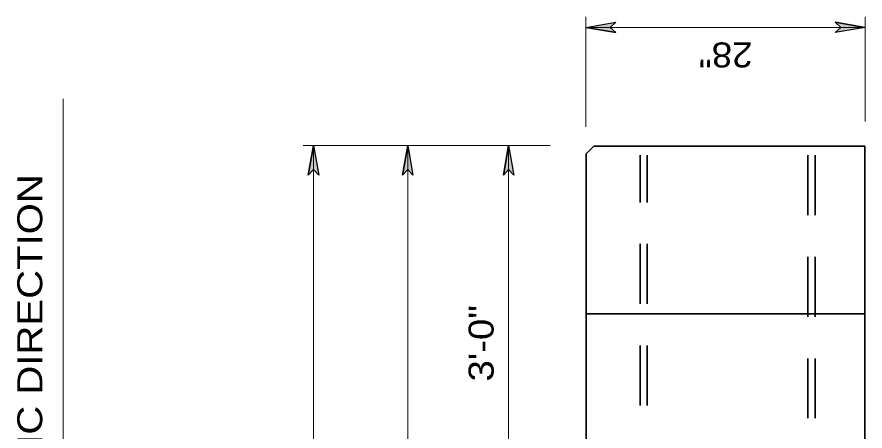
# Model space of a CAD drawing. Extents: x 12.6 to 19.5, y 6.1 to 16.3.
# Drawn here: x 14.828 to 16.866, y 12.348 to 13.343 of the extents above; entities that cross this region are included whole.
import ezdxf
from ezdxf.enums import TextEntityAlignment as Align

# ---------------------------------------------------------------- set-up
doc = ezdxf.new("R2010")
doc.units = 0
doc.header["$LTSCALE"] = 0.024
doc.linetypes.add('LONG_DASHED', pattern=[7.5, 6, -1.5])
for name, color, linetype, lineweight in [('1', 7, 'Continuous', 35), ('10', 7, 'Continuous', 25), ('12', 7, 'Continuous', 53)]:
    doc.layers.add(name, color=color, linetype=linetype, lineweight=lineweight)

msp = doc.modelspace()

# ---------------------------------------------------------------- hatches: boundary and pattern name
at = {"layer": '10'}
for points in [[(16.2671, 13.3051), (16.1956, 13.3177), (16.2671, 13.3303), (16.2536, 13.3177)], [(16.795, 13.3303), (16.8665, 13.3177), (16.795, 13.3051), (16.8085, 13.3177)], [(15.5281, 12.9627), (15.5407, 13.0342), (15.5533, 12.9627), (15.5407, 12.9762)], [(15.7546, 12.9627), (15.7672, 13.0342), (15.7798, 12.9627), (15.7672, 12.9762)], [(15.997, 12.9627), (16.0096, 13.0342), (16.0222, 12.9627), (16.0096, 12.9762)]]:
    msp.add_hatch(color=256, dxfattribs=at).paths.add_polyline_path(points)

# ---------------------------------------------------------------- linework, layer by layer
at = {"layer": '1'}
for p, q in [((16.1964, 13.014), (16.2144, 13.032)), ((16.8664, 13.032), (16.2144, 13.032)), ((16.8664, 13.032), (16.8664, 8.7006)), ((16.8664, 12.6292), (16.1964, 12.6292))]:
    msp.add_line(p, q, dxfattribs=at)
at = {"layer": '1', "linetype": 'LONG_DASHED'}
for p, q in [((16.3256, 11.1894), (16.3256, 13.0105)), ((16.3431, 11.1894), (16.3431, 13.0105)), ((16.7293, 13.0105), (16.7293, 11.4668)), ((16.747, 13.0105), (16.747, 11.4668))]:
    msp.add_line(p, q, dxfattribs=at)
at = {"layer": '1'}
msp.add_lwpolyline([(16.1964, 13.014), (16.1964, 11.1894), (16.8664, 11.1894)], dxfattribs=at)
at = {"layer": '10', "lineweight": 13}
for p, q in [((16.1956, 13.0788), (16.1956, 13.3427)), ((16.8665, 13.0918), (16.8665, 13.3427)), ((16.8665, 13.3177), (16.1956, 13.3177)), ((14.9387, 11.8211), (14.9387, 13.1462)), ((16.1095, 13.0342), (15.5157, 13.0342)), ((15.5407, 13.0342), (15.5407, 11.2575)), ((15.7672, 8.7029), (15.7672, 13.0342)), ((16.0096, 12.1685), (16.0096, 13.0342))]:
    msp.add_line(p, q, dxfattribs=at)
at = {"layer": '10'}
for p, q in [((16.1956, 13.3177), (16.2671, 13.3303)), ((16.1956, 13.3177), (16.2671, 13.3051)), ((16.8665, 13.3177), (16.795, 13.3303)), ((16.8665, 13.3177), (16.795, 13.3051)), ((15.5407, 13.0342), (15.5281, 12.9627)), ((15.5407, 13.0342), (15.5533, 12.9627)), ((15.7672, 13.0342), (15.7546, 12.9627)), ((15.7672, 13.0342), (15.7798, 12.9627)), ((16.0096, 13.0342), (15.997, 12.9627)), ((16.0096, 13.0342), (16.0222, 12.9627))]:
    msp.add_line(p, q, dxfattribs=at)
for points in [[(16.2671, 13.3051), (16.1956, 13.3177), (16.2671, 13.3303), (16.2536, 13.3177)], [(16.795, 13.3303), (16.8665, 13.3177), (16.795, 13.3051), (16.8085, 13.3177)], [(15.5281, 12.9627), (15.5407, 13.0342), (15.5533, 12.9627), (15.5407, 12.9762)], [(15.7546, 12.9627), (15.7672, 13.0342), (15.7798, 12.9627), (15.7672, 12.9762)], [(15.997, 12.9627), (16.0096, 13.0342), (16.0222, 12.9627), (16.0096, 12.9762)]]:
    msp.add_lwpolyline(points, close=True, dxfattribs=at)
for points in [[(16.2671, 13.3051), (16.2536, 13.3177), (16.2671, 13.3303)], [(16.795, 13.3303), (16.8085, 13.3177), (16.795, 13.3051)], [(15.5281, 12.9627), (15.5407, 12.9762), (15.5533, 12.9627)], [(15.7546, 12.9627), (15.7672, 12.9762), (15.7798, 12.9627)], [(15.997, 12.9627), (16.0096, 12.9762), (16.0222, 12.9627)]]:
    msp.add_lwpolyline(points, dxfattribs=at)

# ---------------------------------------------------------------- texts
at = {"layer": '12'}
for s, rotation, width, p in [('28"', 180, 1.1, (16.5961, 13.2815)), ('3\'-0"', 90, 1.15, (15.9736, 12.4669))]:
    msp.add_text(s, height=0.06, rotation=rotation, dxfattribs=dict(at, width=width)).set_placement(p)
at = {"layer": '12', "width": 1.2}
msp.add_text('TRAFFIC DIRECTION', height=0.06, rotation=90, dxfattribs=at).set_placement((14.8887, 12.4836), align=Align.CENTER)

doc.saveas('drawing.dxf')
